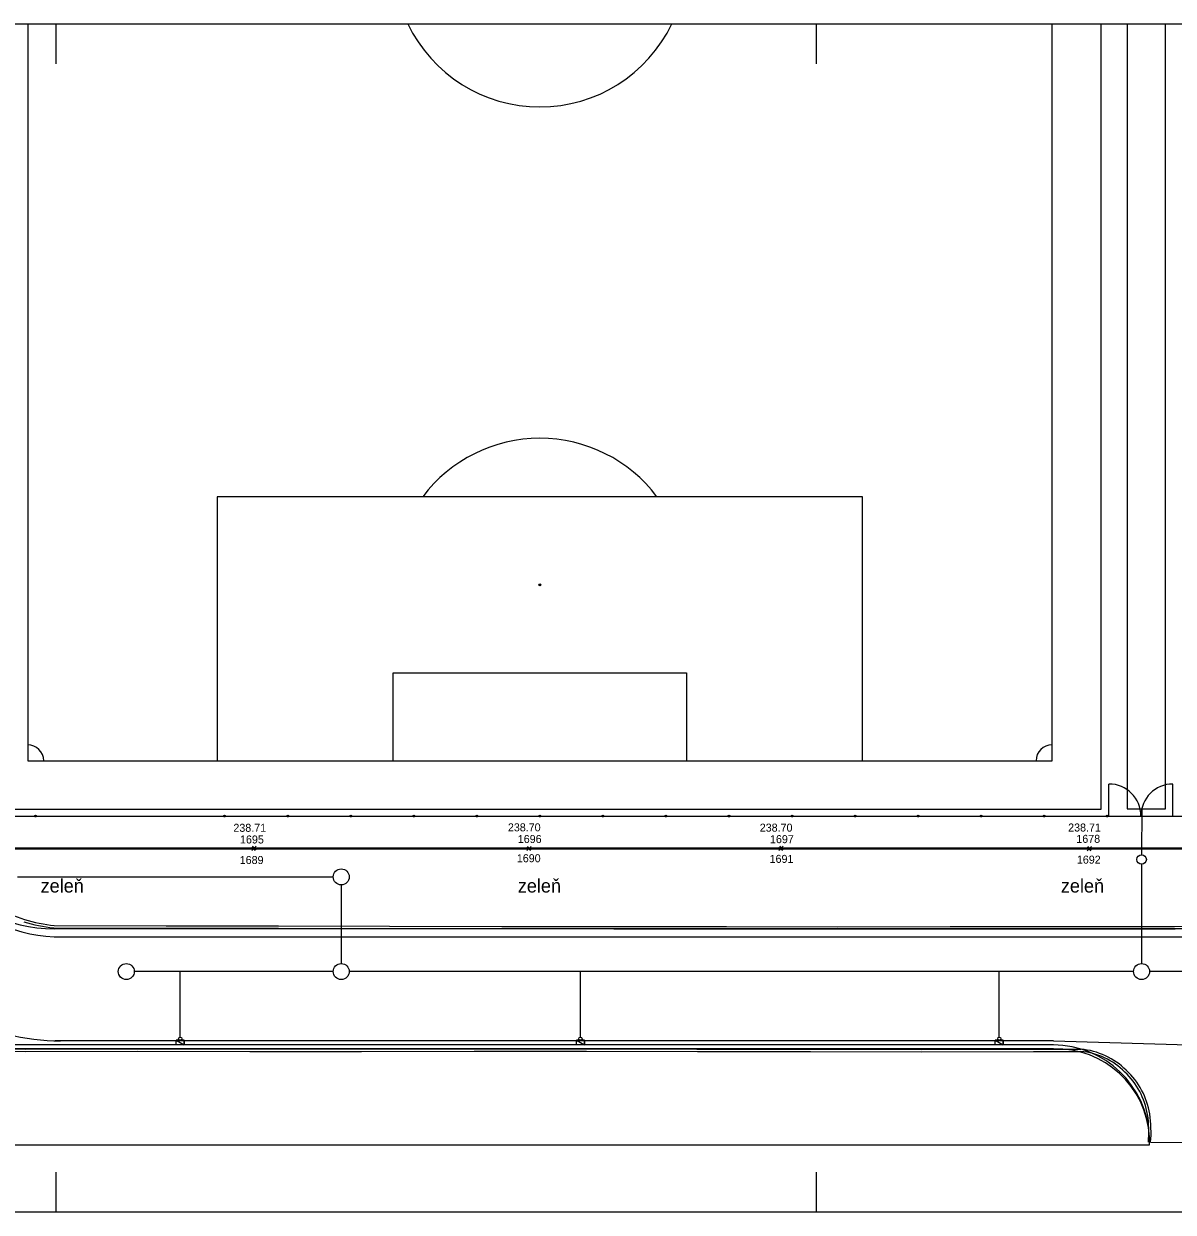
# Model space of a CAD drawing. Extents: x -264165 to -263733, y -1242319 to -1242245.
# Drawn here: x -264114.9 to -264043, y -1242319.2 to -1242244.9 of the extents above; entities that cross this region are included whole.
import ezdxf

# ---------------------------------------------------------------- set-up
doc = ezdxf.new("R2010")
doc.units = 0
for name, color, linetype in [('KFA_BOD_CISLO', 7, 'Continuous'), ('KFA_BOD_SYMBOL', 7, 'Continuous'), ('KFA_BOD_VYSKA', 7, 'Continuous'), ('KFA_SO_20-2_OBRUBNIKY_HORNA_HRANA', 7, 'Continuous'), ('POPIS', 7, 'Continuous'), ('PROJEKT_OBRUBNIKY_KOMUNIKACIE', 7, 'Continuous'), ('PROJEKT_TDZ_VODOROVNE', 7, 'Continuous'), ('RAM_NA_TLAC_1-250', 7, 'Continuous'), ('SITUACIA_DSP_2D', 7, 'Continuous'), ('SO_20-1_OBRUBNIKY_DOLNA_HRANA', 7, 'Continuous'), ('SO_20-1_OBRUBNIKY_DOLNA_HRANA_POMOCNE', 7, 'Continuous'), ('SO_20-1_OBRUBNIKY_HORNA_HRANA', 7, 'Continuous')]:
    doc.layers.add(name, color=color, linetype=linetype)

msp = doc.modelspace()

# ---------------------------------------------------------------- linework, layer by layer
at = {"layer": 'KFA_BOD_SYMBOL'}
for p, q in [((-264100.622, -1242296.595), (-264100.4, -1242296.373)), ((-264100.4, -1242296.595), (-264100.622, -1242296.373)), ((-264100.573, -1242296.546), (-264100.351, -1242296.325)), ((-264100.351, -1242296.546), (-264100.573, -1242296.325)), ((-264083.432, -1242296.596), (-264083.212, -1242296.374)), ((-264083.212, -1242296.596), (-264083.432, -1242296.374)), ((-264083.383, -1242296.546), (-264083.162, -1242296.326)), ((-264083.162, -1242296.546), (-264083.383, -1242296.326)), ((-264067.682, -1242296.589), (-264067.46, -1242296.367)), ((-264067.46, -1242296.589), (-264067.682, -1242296.367)), ((-264067.633, -1242296.539), (-264067.411, -1242296.319)), ((-264067.411, -1242296.539), (-264067.633, -1242296.319)), ((-264048.422, -1242296.6), (-264048.201, -1242296.379)), ((-264048.201, -1242296.6), (-264048.422, -1242296.379)), ((-264048.373, -1242296.551), (-264048.152, -1242296.329)), ((-264048.152, -1242296.551), (-264048.373, -1242296.329))]:
    msp.add_line(p, q, dxfattribs=at)
at = {"layer": 'KFA_SO_20-2_OBRUBNIKY_HORNA_HRANA'}
for points in [[(-264120.439, -1242271.461), (-264120.452, -1242296.479), (-264100.511, -1242296.484), (-264083.322, -1242296.485), (-264067.571, -1242296.478), (-264048.312, -1242296.489)], [(-264120.39, -1242271.447), (-264120.403, -1242296.43), (-264100.462, -1242296.435), (-264083.273, -1242296.436), (-264067.522, -1242296.429), (-264048.263, -1242296.44)], [(-264048.312, -1242296.489), (-264028.434, -1242296.487), (-264007.811, -1242296.484), (-263989.348, -1242296.492), (-263970.175, -1242296.491), (-263970.185, -1242293.475)], [(-264048.263, -1242296.44), (-264028.48, -1242296.445), (-264007.857, -1242296.442), (-263989.394, -1242296.45), (-263970.221, -1242296.449), (-263970.229, -1242293.474)]]:
    msp.add_lwpolyline(points, dxfattribs=at)
at = {"layer": 'PROJEKT_OBRUBNIKY_KOMUNIKACIE'}
for p, q in [((-263971.068, -1242301.482), (-264112.961, -1242301.482)), ((-264050.531, -1242308.982), (-264119.571, -1242308.982)), ((-264044.531, -1242314.982), (-264044.531, -1242314.482)), ((-264115.886, -1242314.982), (-264044.531, -1242314.982))]:
    msp.add_line(p, q, dxfattribs=at)
for points in [[(-264047.568, -1242244.935), (-264047.568, -1242294.032), (-264117.668, -1242294.032), (-264117.668, -1242244.935)], [(-263965.143, -1242296.432), (-264120.018, -1242296.432), (-264120.282, -1242296.432)]]:
    msp.add_lwpolyline(points, dxfattribs=at)
for centre, radius, start, end in [((-264112.961, -1242292.482), 9, 215.72401, 270), ((-264050.347, -1242314.804), 5.825, 3.17009, 91.80902)]:
    msp.add_arc(centre, radius, start, end, dxfattribs=at)
at = {"layer": 'PROJEKT_TDZ_VODOROVNE'}
for p, q in [((-264112.961, -1242301.982), (-263971.806, -1242301.982)), ((-264050.531, -1242308.482), (-264112.906, -1242308.482)), ((-264050.531, -1242308.482), (-264032.141, -1242309.015))]:
    msp.add_line(p, q, dxfattribs=at)
for centre, radius, start, end in [((-264112.56, -1242292.924), 9.068, 215.87399, 267.4682), ((-264112.435, -1242293.84), 14.642, 217.62012, 269.49568)]:
    msp.add_arc(centre, radius, start, end, dxfattribs=at)
at = {"layer": 'RAM_NA_TLAC_1-250'}
for p, q in [((-264112.863, -1242244.935), (-264112.863, -1242247.435)), ((-264065.363, -1242244.935), (-264065.363, -1242247.435)), ((-264112.863, -1242316.685), (-264112.863, -1242319.185)), ((-264065.363, -1242316.685), (-264065.363, -1242319.185))]:
    msp.add_line(p, q, dxfattribs=at)
msp.add_lwpolyline([(-264165.363, -1242244.935), (-263732.863, -1242244.935), (-263732.863, -1242319.185), (-264165.363, -1242319.185)], close=True, dxfattribs=at)
at = {"layer": 'SITUACIA_DSP_2D'}
for p, q in [((-264114.618, -1242244.935), (-264114.618, -1242290.982)), ((-264050.618, -1242290.982), (-264050.618, -1242244.935)), ((-264047.568, -1242244.935), (-264047.568, -1242244.935)), ((-264047.568, -1242244.935), (-264047.568, -1242294.032)), ((-264045.927, -1242244.935), (-264045.927, -1242293.982)), ((-264043.527, -1242293.982), (-264043.527, -1242244.935)), ((-264062.458, -1242274.482), (-264102.778, -1242274.482)), ((-264102.778, -1242274.482), (-264102.778, -1242290.982)), ((-264062.458, -1242290.982), (-264062.458, -1242274.482)), ((-264091.778, -1242290.982), (-264091.778, -1242285.482)), ((-264091.778, -1242285.482), (-264073.458, -1242285.482)), ((-264073.458, -1242285.482), (-264073.458, -1242290.982)), ((-264114.618, -1242290.982), (-264050.618, -1242290.982)), ((-264047.068, -1242294.432), (-264047.068, -1242292.432)), ((-264043.068, -1242294.432), (-264043.068, -1242292.432)), ((-264118.068, -1242294.432), (-264045.118, -1242294.432)), ((-264047.568, -1242294.032), (-264117.668, -1242294.032)), ((-264114.069, -1242294.432), (-264114.189, -1242294.432)), ((-264114.129, -1242294.492), (-264114.129, -1242294.372)), ((-264102.252, -1242294.432), (-264102.372, -1242294.432)), ((-264102.312, -1242294.492), (-264102.312, -1242294.372)), ((-264098.313, -1242294.432), (-264098.433, -1242294.432)), ((-264098.373, -1242294.492), (-264098.373, -1242294.372)), ((-264094.374, -1242294.432), (-264094.494, -1242294.432)), ((-264094.434, -1242294.492), (-264094.434, -1242294.372)), ((-264090.436, -1242294.432), (-264090.556, -1242294.432)), ((-264090.496, -1242294.492), (-264090.496, -1242294.372)), ((-264086.497, -1242294.432), (-264086.617, -1242294.432)), ((-264086.557, -1242294.492), (-264086.557, -1242294.372)), ((-264082.558, -1242294.432), (-264082.678, -1242294.432)), ((-264082.618, -1242294.492), (-264082.618, -1242294.372)), ((-264078.619, -1242294.432), (-264078.739, -1242294.432)), ((-264078.679, -1242294.492), (-264078.679, -1242294.372)), ((-264074.68, -1242294.432), (-264074.8, -1242294.432)), ((-264074.74, -1242294.492), (-264074.74, -1242294.372)), ((-264070.741, -1242294.432), (-264070.861, -1242294.432)), ((-264070.801, -1242294.492), (-264070.801, -1242294.372)), ((-264066.802, -1242294.432), (-264066.922, -1242294.432)), ((-264066.862, -1242294.492), (-264066.862, -1242294.372)), ((-264062.863, -1242294.432), (-264062.983, -1242294.432)), ((-264062.923, -1242294.492), (-264062.923, -1242294.372)), ((-264058.924, -1242294.432), (-264059.044, -1242294.432)), ((-264058.984, -1242294.492), (-264058.984, -1242294.372)), ((-264054.986, -1242294.432), (-264055.106, -1242294.432)), ((-264055.046, -1242294.492), (-264055.046, -1242294.372)), ((-264051.047, -1242294.432), (-264051.167, -1242294.432)), ((-264051.107, -1242294.492), (-264051.107, -1242294.372)), ((-264047.108, -1242294.432), (-264047.228, -1242294.432)), ((-264047.168, -1242294.492), (-264047.168, -1242294.372)), ((-264045.927, -1242293.982), (-264043.527, -1242293.982)), ((-264045.568, -1242294.432), (-264044.568, -1242294.432)), ((-264045.118, -1242294.432), (-263972.068, -1242294.432)), ((-264045.017, -1242293.982), (-264045.027, -1242296.847)), ((-264045.027, -1242297.447), (-264045.027, -1242303.647)), ((-264115.254, -1242298.236), (-264095.527, -1242298.236)), ((-264095.027, -1242298.736), (-264095.027, -1242303.647)), ((-263971.068, -1242301.482), (-264112.961, -1242301.482)), ((-264095.527, -1242304.147), (-264107.955, -1242304.147)), ((-264105.085, -1242308.242), (-264105.085, -1242304.147)), ((-264045.527, -1242304.147), (-264094.527, -1242304.147)), ((-264080.085, -1242308.242), (-264080.085, -1242304.147)), ((-264053.913, -1242308.242), (-264053.913, -1242304.147)), ((-264004.396, -1242304.147), (-264044.527, -1242304.147)), ((-264105.335, -1242308.442), (-264104.835, -1242308.442)), ((-264105.335, -1242308.732), (-264105.335, -1242308.442)), ((-264105.335, -1242308.442), (-264104.835, -1242308.732)), ((-264105.335, -1242308.442), (-264104.835, -1242308.732)), ((-264104.835, -1242308.442), (-264105.335, -1242308.442)), ((-264104.835, -1242308.442), (-264104.835, -1242308.732)), ((-264104.835, -1242308.732), (-264104.835, -1242308.442)), ((-264080.335, -1242308.442), (-264079.835, -1242308.442)), ((-264080.335, -1242308.732), (-264080.335, -1242308.442)), ((-264080.335, -1242308.442), (-264079.835, -1242308.732)), ((-264080.335, -1242308.442), (-264079.835, -1242308.732)), ((-264079.835, -1242308.442), (-264080.335, -1242308.442)), ((-264079.835, -1242308.442), (-264079.835, -1242308.732)), ((-264079.835, -1242308.732), (-264079.835, -1242308.442)), ((-264054.163, -1242308.442), (-264053.663, -1242308.442)), ((-264054.163, -1242308.732), (-264054.163, -1242308.442)), ((-264054.163, -1242308.442), (-264053.663, -1242308.732)), ((-264054.163, -1242308.442), (-264053.663, -1242308.732)), ((-264053.663, -1242308.442), (-264054.163, -1242308.442)), ((-264053.663, -1242308.442), (-264053.663, -1242308.732)), ((-264053.663, -1242308.732), (-264053.663, -1242308.442)), ((-264050.531, -1242308.732), (-264119.75, -1242308.732)), ((-264104.835, -1242308.732), (-264105.335, -1242308.732)), ((-264079.835, -1242308.732), (-264080.335, -1242308.732)), ((-264053.663, -1242308.732), (-264054.163, -1242308.732)), ((-264044.531, -1242314.982), (-264044.531, -1242314.482)), ((-264115.886, -1242314.982), (-264044.531, -1242314.982))]:
    msp.add_line(p, q, dxfattribs=at)
msp.add_lwpolyline([(-263965.143, -1242296.432), (-264120.018, -1242296.432), (-264120.282, -1242296.432)], dxfattribs=at)
for centre, radius in [((-264082.618, -1242279.982), 0.06), ((-264114.129, -1242294.432), 0.06), ((-264102.312, -1242294.432), 0.06), ((-264098.373, -1242294.432), 0.06), ((-264094.434, -1242294.432), 0.06), ((-264090.496, -1242294.432), 0.06), ((-264086.557, -1242294.432), 0.06), ((-264082.618, -1242294.432), 0.06), ((-264078.679, -1242294.432), 0.06), ((-264074.74, -1242294.432), 0.06), ((-264070.801, -1242294.432), 0.06), ((-264066.862, -1242294.432), 0.06), ((-264062.923, -1242294.432), 0.06), ((-264058.984, -1242294.432), 0.06), ((-264055.046, -1242294.432), 0.06), ((-264051.107, -1242294.432), 0.06), ((-264047.168, -1242294.432), 0.06), ((-264045.027, -1242297.147), 0.3), ((-264095.027, -1242298.236), 0.5), ((-264108.455, -1242304.147), 0.5), ((-264095.027, -1242304.147), 0.5), ((-264045.027, -1242304.147), 0.5), ((-264105.085, -1242308.342), 0.1), ((-264080.085, -1242308.342), 0.1), ((-264053.913, -1242308.342), 0.1)]:
    msp.add_circle(centre, radius, dxfattribs=at)
for centre, radius, start, end in [((-264082.618, -1242240.982), 9.15, 205.59455, 334.40545), ((-264082.618, -1242279.982), 9.15, 36.94821, 143.05179), ((-264082.618, -1242279.982), 0.0303, 90, 270), ((-264082.618, -1242279.982), 0.0303, 270, 90), ((-264114.618, -1242290.982), 1, 0, 90), ((-264050.618, -1242290.982), 1, 90, 180), ((-264047.068, -1242294.432), 2, 0, 90), ((-264043.068, -1242294.432), 2, 90, 180), ((-264112.961, -1242292.482), 9, 215.72401, 270), ((-264050.561, -1242314.769), 6.037, 2.72538, 89.71237)]:
    msp.add_arc(centre, radius, start, end, dxfattribs=at)
at = {"layer": 'SO_20-1_OBRUBNIKY_DOLNA_HRANA'}
for points in [[(-264124.808, -1242301.762), (-264122.825, -1242304.519), (-264119.622, -1242308.973), (-264114.767, -1242308.991), (-264107.775, -1242308.984), (-264100.725, -1242308.982), (-264086.721, -1242308.982)], [(-264112.987, -1242301.418), (-264105.969, -1242301.433), (-264098.941, -1242301.446), (-264091.986, -1242301.46), (-264084.992, -1242301.468)], [(-264084.992, -1242301.468), (-264078.002, -1242301.482), (-264070.986, -1242301.489), (-264064.021, -1242301.482), (-264056.978, -1242301.482), (-264049.977, -1242301.481), (-264042.921, -1242301.475), (-264035.92, -1242301.469), (-264028.972, -1242301.456), (-264022.003, -1242301.442), (-264014.974, -1242301.438), (-264007.969, -1242301.429), (-264000.909, -1242301.426), (-263993.952, -1242301.425)], [(-264086.721, -1242308.982), (-264079.708, -1242308.985), (-264072.821, -1242308.988), (-264065.744, -1242308.997), (-264058.784, -1242309.009), (-264051.779, -1242308.995), (-264048.812, -1242308.996)]]:
    msp.add_lwpolyline(points, dxfattribs=at)
for centre, major_axis, ratio, start_param, end_param in [((-264111.865, -1242291.044), (9.276, -4.796), 0.999118, 4.898081, 5.081552), ((-264049.236, -1242313.601), (-0.121, 4.623), 0.99973, 5.475924, 6.165207), ((-264049.204, -1242313.793), (-3.668, 3.021), 0.997623, 3.991062, 4.653737), ((-264048.266, -1242313.635), (-0.777, 5.296), 0.708679, 4.385578, 4.720857)]:
    msp.add_ellipse(centre, major_axis=major_axis, ratio=ratio, start_param=start_param, end_param=end_param, dxfattribs=at)
at = {"layer": 'SO_20-1_OBRUBNIKY_DOLNA_HRANA_POMOCNE'}
msp.add_line((-264044.462, -1242314.814), (-264038.521, -1242314.824), dxfattribs=at)
at = {"layer": 'SO_20-1_OBRUBNIKY_HORNA_HRANA'}
for points in [[(-264124.926, -1242301.846), (-264122.945, -1242304.592), (-264119.692, -1242309.125), (-264114.755, -1242309.139), (-264107.766, -1242309.132), (-264100.735, -1242309.134), (-264093.764, -1242309.133), (-264086.73, -1242309.126)], [(-264112.959, -1242301.277), (-264105.975, -1242301.287), (-264098.94, -1242301.301), (-264092.01, -1242301.314), (-264084.994, -1242301.327)], [(-264084.994, -1242301.327), (-264077.993, -1242301.335), (-264070.958, -1242301.339), (-264063.998, -1242301.345), (-264056.974, -1242301.334), (-264049.976, -1242301.332), (-264042.963, -1242301.324), (-264035.917, -1242301.32), (-264028.967, -1242301.31), (-264022.019, -1242301.3), (-264014.954, -1242301.285), (-264007.975, -1242301.28), (-264000.942, -1242301.277), (-263993.949, -1242301.276)], [(-264086.73, -1242309.126), (-264079.711, -1242309.131), (-264072.777, -1242309.148), (-264065.719, -1242309.143), (-264058.778, -1242309.157), (-264051.772, -1242309.139), (-264048.834, -1242309.14)]]:
    msp.add_lwpolyline(points, dxfattribs=at)
for centre, major_axis, ratio, start_param, end_param in [((-264110.586, -1242287.673), (-7.289, -11.816), 0.999902, 6.242047, 6.527042), ((-264111.762, -1242290.774), (10.595, -0.535), 0.996454, 4.471564, 4.649627), ((-264049.219, -1242313.585), (0.537, 4.429), 0.999772, 5.618541, 6.31756), ((-264049.294, -1242313.843), (-3.584, 3.057), 0.997273, 4.013713, 4.66096), ((-264047.913, -1242313.599), (-0.698, 4.901), 0.666836, 4.368269, 4.724889)]:
    msp.add_ellipse(centre, major_axis=major_axis, ratio=ratio, start_param=start_param, end_param=end_param, dxfattribs=at)

# ---------------------------------------------------------------- texts
at = {"layer": 'KFA_BOD_CISLO'}
for s, p in [('1695', (-264101.352, -1242296.147)), ('1696', (-264083.997, -1242296.116)), ('1697', (-264068.241, -1242296.128)), ('1678', (-264049.101, -1242296.108)), ('1689', (-264101.37, -1242297.43)), ('1690', (-264084.057, -1242297.32)), ('1691', (-264068.264, -1242297.359)), ('1692', (-264049.067, -1242297.407))]:
    msp.add_text(s, height=0.5, dxfattribs=at).set_placement(p)
at = {"layer": 'KFA_BOD_VYSKA'}
for s, p in [('238.71', (-264101.765, -1242295.418)), ('238.70', (-264084.615, -1242295.389)), ('238.70', (-264068.88, -1242295.407)), ('238.71', (-264049.613, -1242295.399))]:
    msp.add_text(s, height=0.5, dxfattribs=at).set_placement(p)
at = {"layer": 'POPIS'}
for p in [(-264113.809, -1242299.211), (-264083.995, -1242299.211), (-264050.067, -1242299.211)]:
    msp.add_text('zeleň', height=0.8438, dxfattribs=at).set_placement(p)

doc.saveas('drawing.dxf')
